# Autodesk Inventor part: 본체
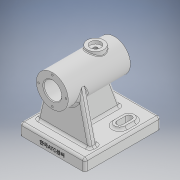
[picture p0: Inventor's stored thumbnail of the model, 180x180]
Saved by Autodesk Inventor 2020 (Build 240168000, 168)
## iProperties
Created: 2021-11
Part Number: 본체
Material: 일반
Document SubType Name: Modeling
Designer: user
Density: 1 g/cm^3
Appearance: 기본값
Mass: 231.26 g
Surface Area: 507.653 cm^2
Volume: 231.26 cm^3
Author: user
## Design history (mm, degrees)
sketch "스케치1"
  geometry: C1 r 21 at (0, 0); 1 further point
  constraints: 1 centre point, 1 coincident
  dimensions: "d0" = 42 diameter of C1
extrude "돌출1" new body sketch "스케치1" stored distance "d1" = 82; taper "d2" = 0 deg
node "작업 평면1"
sketch "스케치6"
  geometry: L1 (-43, -59)-(43, -59); L2 (43, -59)-(43, 41); L3 (43, 41)-(-43, 41); L4 (-43, 41)-(-43, -59); L5 (-43, -59)-(43, 41); L6 (43, -59)-(-43, 41); L7 (21, 41)-(-21, 41) reference; 2 further points
  constraints: 12 end point, 2 midpoint, 2 parallel, 1 horizontal, 1 perpendicular
  dimensions: "d17" = 86 distance of L3.end L2.end; "d18" = 100 distance of L2.end L1.end; "d19" = 0 distance between parallel lines of L7 L3; "d20" = 43 distance from line of L4 point (0, 0)
extrude "돌출4" join sketch "스케치6" distance "d21" = 15; taper "d22" = 0 deg
node "작업 평면3"
sketch "스케치7"
  geometry: L1 (43, -57)-(43, -72) reference; L2 (43, -72)-(-43, -72) reference; L3 (-43, -72)-(-43, -57) reference; L4 (-43, -57)-(43, -57) reference; L5 (20.441, 4.814)-(35, -57); L6 (43, -57)-(-43, -57) reference; L7 (-20.441, 4.814)-(-35, -57); L8 (-35, -57)-(35, -57); L9 (43, -72)-(43, -57) reference; C1 r 21 at (0, 0) reference; A1 r 21 centre (0, 0) between (20.441, 4.814) and (-20.441, 4.814) reference; A2 r 21 centre (0, 0) between (-20.441, 4.814) and (20.441, 4.814); 5 further points
  constraints: 6 end point, 4 point on circle, 2 point on line, 2 tangent, 1 centre point, 1 coincident, 1 collinear
  dimensions: "d89" = 8 distance from line of L3 L7.end; "d90" = 8 distance from line of L9 L5.end
extrude "돌출5" join sketch "스케치7" distance "d26" = 10; taper "d27" = 0 deg
sketch "스케치8"
  geometry: L1 (21, -41)-(-21, -41) reference; L2 (-21, -41)-(-21, 16) reference; L3 (-21, 16)-(-57, 16) reference; L4 (-57, 16)-(-57, -59) reference; L5 (-57, -59)-(-72, -59) reference; L6 (-72, -59)-(-72, 41) reference; L7 (-72, 41)-(-57, 41) reference; L8 (-57, 41)-(-57, 26) reference; L9 (-57, 26)-(-21, 26) reference; L10 (-21, 26)-(-21, 41) reference; L11 (-21, 41)-(21, 41) reference; L12 (21, 41)-(21, -41) reference; L13 (-21, -41)-(-21, 41) reference; L14 (-21, -30.897)-(-57, -44); L15 (-57, 41)-(-57, -59) reference; 1 further point
  constraints: 2 end point, 2 point on line
  dimensions: "d28" = 15 distance from line of L5 L14.end; "d29" = 70 deg angle of L4 L14
feature "리브1" sketch "스케치8" dims "d30" = 1, "d31" = 10, "d32" = 0, "d33" = 0, "d34" = 1, "d35" = 1
sketch "스케치9"
  geometry: C1 r 11.5 at (0, 0); 1 further point
  constraints: 1 centre point, 1 coincident
  dimensions: "d36" = 23 diameter of C1
extrude "돌출6" cut sketch "스케치9" distance "d37" = 20; taper "d38" = 0 deg
sketch "스케치10"
  geometry: C1 r 14.5 at (0, 0); 1 further point
  constraints: 1 centre point, 1 coincident
  dimensions: "d39" = 29 diameter of C1
extrude "돌출7" cut sketch "스케치10" distance "d40" = 62; taper "d41" = 0 deg
fillet "모깎기1" dims "d42" = 3
sketch "스케치11"
  geometry: L1 (27, 33)-(27, 21); L2 (20, 33)-(20, 21); L3 (34, 21)-(34, 33); L4 (40, 59)-(-40, 59) reference; L5 (43, -38)-(43, 56) reference; A1 r 7 centre (27, 33) between (34, 33) and (20, 33); A2 r 7 centre (27, 21) between (20, 21) and (34, 21); 2 further points
  constraints: 8 end point, 4 point on circle, 4 tangent, 2 centre point, 1 midpoint, 1 parallel, 1 vertical
  dimensions: "d43" = 12 distance of L1.start L1.end; "d44" = 14 diameter of A2; "d45" = 26 distance from line of L4 L1.start; "d46" = 16 distance from line of L5 L1.start
extrude "돌출8" join sketch "스케치11" distance "d47" = 3; taper "d48" = 0 deg
sketch "스케치12"
  geometry: L1 (0, 0)-(0, 12); L2 (4, 0)-(4, 12); L3 (-4, 12)-(-4, 0); A1 r 7 centre (0, 0) between (-7, 0) and (7, 0) reference; A2 r 7 centre (0, 12) between (7, 12) and (-7, 12) reference; A3 r 4 centre (0, 0) between (-4, 0) and (4, 0); A4 r 4 centre (0, 12) between (4, 12) and (-4, 12); 2 further points
  constraints: 8 end point, 4 point on circle, 4 tangent, 2 centre point, 1 midpoint, 1 parallel, 1 vertical
  dimensions: "d49" = 8 diameter of A4
extrude "돌출9" cut sketch "스케치12" extent not by distance; stored distance "d50" = 0; taper "d51" = 0 deg
node "작업 평면4"
sketch "스케치13"
  geometry: L1 (-21, -41)-(21, -41) reference; C1 r 11 at (0, -16); 1 further point
  constraints: 1 centre point, 1 vertical alignment
  dimensions: "d53" = 22 diameter of C1; "d54" = 25 distance from line of L1 C1.centre
extrude "돌출10" join sketch "스케치13" stored distance "d55" = 3; taper "d56" = 0 deg
sketch "스케치14"
  geometry: L1 (21, 25)-(-21, 25) reference; 2 further points
  constraints: 1 vertical alignment
  dimensions: "d57" = 25 distance from line of L1 point (0, 0)
hole "구멍1" sketch "스케치14" at (0, 0) diameter "d58" = 4.917; stored, may be unused: countersink angle "d62" = 90 deg, drill point angle "d64" = 0 deg; dims "d59" = 17, "d60" = 14, "d61" = 4, "d63" = 17.1
sketch "스케치16" dims "d65" = 36
  geometry: 3 further points
  constraints: 2 vertical alignment, 1 coincident, 2 other
hole "구멍2" sketch "스케치16" at (0, 18) diameter "d66" = 2.459; stored, may be unused: countersink angle "d70" = 90 deg, drill point angle "d72" = 118 deg; dims "d67" = 8, "d68" = 14, "d69" = 4, "d71" = 10
fillet "모깎기2" dims "d76" = 3
fillet "모깎기3" dims "d77" = 3
fillet "모깎기4" dims "d78" = 3
fillet "모깎기5" dims "d79" = 3
fillet "모깎기6" dims "d80" = 3
fillet "모깎기7" dims "d81" = 3
fillet "모깎기8" dims "d82" = 1
chamfer "모따기1" distance "d83" = 1; stored, may be unused: second distance "d84" = 2, angle "d85" = 45 deg
sketch "스케치17"
  geometry: L1 (83, 0)-(80, 0) reference; 2 further points
  constraints: 1 vertical alignment, 1 other
  dimensions: "d86" = 6 distance from line of L1 point (40, 6)
extrude "돌출11" join sketch "스케치17" distance "d87" = 0.5; taper "d88" = 0 deg
node "솔리드1"
mirror "미러1"
mirror "미러2"
pattern_circular "원형 패턴1" dims angle "d74" = 360 deg
mirror "미러3"
node "절단 모서리 투영2"
node "절단 모서리 투영3"
feature "A9D066F2-1C7D-4E18-AEED-F7BC21143FA4" dims "d58" = 4.917, "d59" = 17, "d60" = 14, "d61" = 4, "d62" = 90 deg, "d63" = 17.1, "d64" = 0
other parameters: "d3" = -72, "d23" = 26, "d52" = 24
